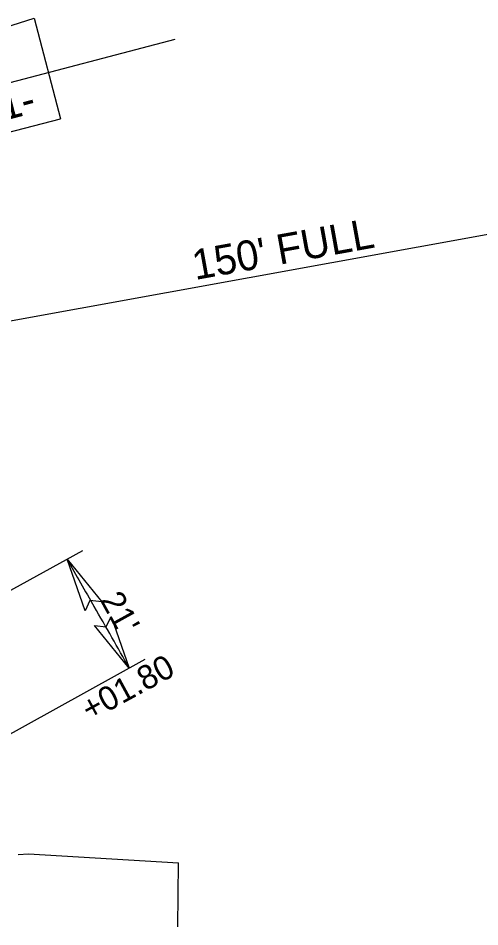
# Model space of a CAD drawing. Extents: x 1616561 to 1622460, y 896726 to 899651.
# Drawn here: x 1621074.7 to 1621151.6, y 897923.3 to 898074.8 of the extents above; entities that cross this region are included whole.
import ezdxf

# ---------------------------------------------------------------- set-up
doc = ezdxf.new("R2010")
doc.units = 0
for name, color, linetype in [('Prop Dimension', 7, 'Continuous'), ('Prop Terminator CELL', 7, 'Continuous'), ('Scratch_Level_1', 7, 'Continuous'), ('Sheet Cutting Line CELL', 7, 'Continuous'), ('Sheet Sticker Preliminary CELL', 7, 'Continuous')]:
    doc.layers.add(name, color=color, linetype=linetype)

msp = doc.modelspace()

# ---------------------------------------------------------------- linework, layer by layer
at = {"layer": 'Prop Dimension'}
msp.add_line((1621037.09, 898017.79), (1621184.69, 898044.51), dxfattribs=at)
at = {"layer": 'Prop Terminator CELL'}
for p, q in [((1621052.21, 898066.85), (1621077.33, 898074.8)), ((1621077.33, 898074.8), (1621081.72, 898058.02)), ((1621056.25, 898051.37), (1621081.72, 898058.02)), ((1621074.68, 897935.35), (1621076.42, 897935.44)), ((1621076.42, 897935.44), (1621101.41, 897933.95)), ((1621101.32, 897923.27), (1621101.41, 897933.95))]:
    msp.add_line(p, q, dxfattribs=at)
for points in [[(1621085.83, 897975.97), (1621082.83, 897984.6), (1621088.61, 897977.45), (1621086.65, 897977.69)], [(1621090.17, 897975.01), (1621093.18, 897966.39), (1621087.4, 897973.53), (1621089.35, 897973.3)]]:
    msp.add_lwpolyline(points, close=True, dxfattribs=at)
msp.add_arc((1620559.89, 897670.89), 545, 15.403, 30.1014, dxfattribs=at)
at = {"layer": 'Sheet Cutting Line CELL'}
msp.add_line((1621054.23, 898059.11), (1621100.87, 898071.3), dxfattribs=at)
at = {"layer": 'Sheet Sticker Preliminary CELL'}
for p, q in [((1621028.67, 897954.64), (1621085.45, 897986.05)), ((1621095.81, 897967.84), (1621039.23, 897936.49))]:
    msp.add_line(p, q, dxfattribs=at)
for centre, radius, start, end in [((1621481.42, 898206.77), 456.33, 209.1354, 210.2822), ((1620559.89, 897670.89), 609.69, 28.99083, 30.10143)]:
    msp.add_arc(centre, radius, start, end, dxfattribs=at)

# ---------------------------------------------------------------- texts
at = {"layer": 'Prop Dimension'}
msp.add_text("150' FULL", height=5, rotation=10.2599, dxfattribs=at).set_placement((1621104.18, 898031.13))
at = {"layer": 'Scratch_Level_1'}
msp.add_text('-Y3A D1-', height=5, rotation=14.6458, dxfattribs=at).set_placement((1621051.31, 898052.19))
at = {"layer": 'Sheet Sticker Preliminary CELL'}
for s, rotation, p in [("21'", 298.9546, (1621088.25, 897977.79)), ('+01.80', 28.5892, (1621086.62, 897957.47))]:
    msp.add_text(s, height=4, rotation=rotation, dxfattribs=at).set_placement(p)

doc.saveas('drawing.dxf')
